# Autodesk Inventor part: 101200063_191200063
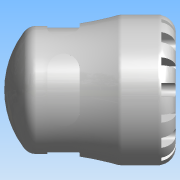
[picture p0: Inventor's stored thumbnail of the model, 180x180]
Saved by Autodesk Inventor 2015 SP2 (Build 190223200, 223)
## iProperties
Created: 2016-12
Part Number: 101200063_191200063
Material: PVC-Piping
Description: PLASSON END PLUG 63 SERIES 1
Document SubType Name: Modeling
Designer: KIM
Mass: 57.8335 g
Surface Area: 121.129 cm^2
Volume: 41.3096 cm^3
Density: 1.4 g/cm^3
Appearance: Smooth - White
Author: KIM
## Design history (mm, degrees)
derived "1012.ipt"
feature "Solid1::1012.ipt"
tag "TaggingFeature1"
body "Solid1"
other parameters: "d0" = 117, "d1" = 38.22, "d2" = 63, "d3" = 78.75, "d4" = 103, "d6" = 91, "d7" = 100.1, "d8" = 87.55, "d13" = 9.7, "d14" = 9.7, "d15" = 0, "d17" = 360 deg, "d19" = 8 deg, "d20" = 1.26, "d21" = 1.26, "d22" = 8 deg, "d24" = 0, "d26" = 360 deg, "d32" = 10.3, "d33" = 10.3, "d34" = 13.86, "d35" = 22.05, "d36" = 19.012, "d37" = 0, "d42" = 360 deg, "d45" = 18.7425, "d46" = 1.26, "d48" = 0, "d49" = 1.03, "d_" = 63, "E_" = 103, "H_" = 117, "l_" = 91, "d9" = 12.125, "d11" = 103, "d12" = 78.75
